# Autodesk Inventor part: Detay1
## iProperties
Company: Autodesk, Inc.
Shininess: 64.0
Length Units: 11269
Angle Units: 11279
Time Units: 11290
Mass Units: 11283
Length Display Precision: 3
Angle Display Precision: 2
Compacted: True
Part Number: Detay1
Document SubType Name: Modeling
Created: 2003-11
Catalog Web Link: www.autodesk.com
Vendor: Autodesk, Inc.
Designer: Administrator
Manufacturer: Standard
Standards Organization: Custom
Density: 1 g/cm^3
Density: 0.0
Volumn: 0.0
Area: 0.0
PropertySet Name: Model Information
Control State: 0
Master: False
Checked Out: False
Author: Administrator
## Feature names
1. Extrusion1
2. Extrusion2
3. Mirror1
4. Hole1
5. Extrusion4
6. Mirror2
7. Chamfer1
8. Chamfer2
9. Fillet1
10. Revolution1
11. Extrusion7
12. Extrusion8
13. Extrusion9
14. Extrusion10
15. Fillet2
16. Fillet3
17. Extrusion11
18. Revolution2
19. Revolution3
20. Hole3
21. Hole4
22. Revolution4
23. Revolution5
24. Extrusion12
25. Hole5
26. Mirror4
